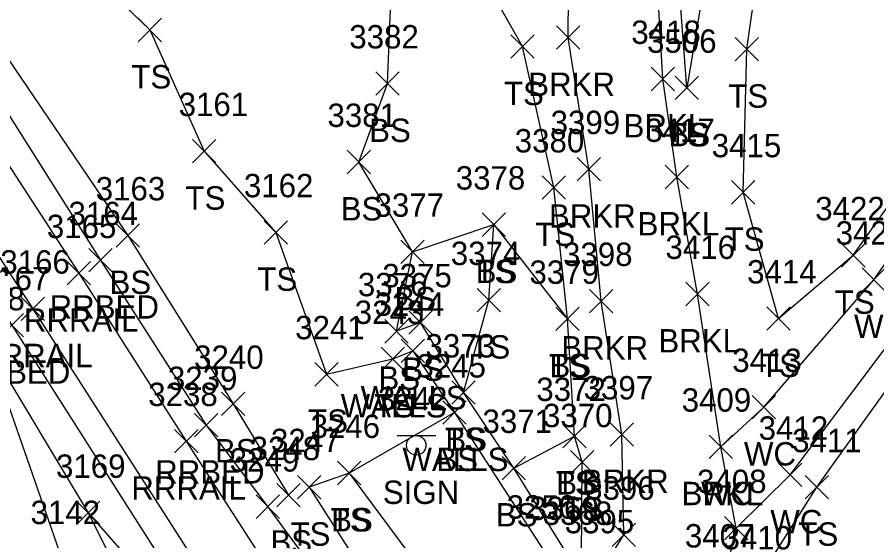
# Model space of a CAD drawing. Extents: x 1505656 to 1508446, y 700805 to 703031.
# Drawn here: x 1506556.2 to 1506629.8, y 701671.8 to 701716.6 of the extents above; entities that cross this region are included whole.
import ezdxf

# ---------------------------------------------------------------- set-up
doc = ezdxf.new("R2010")
doc.units = 0
for name, color, linetype in [('L_A', 7, 'Continuous'), ('L_I', 7, 'Continuous'), ('L_TIC', 7, 'Continuous'), ('LAWE', 7, 'Continuous'), ('LELB', 7, 'Continuous'), ('LWS', 7, 'Continuous'), ('R_A', 7, 'Continuous'), ('R_I', 7, 'Continuous'), ('R_TIC', 7, 'Continuous'), ('RR', 7, 'Continuous'), ('RRB', 7, 'Continuous'), ('S_A', 7, 'Continuous'), ('S_I', 7, 'Continuous'), ('SSGN', 7, 'Continuous')]:
    doc.layers.add(name, color=color, linetype=linetype)

msp = doc.modelspace()

# ---------------------------------------------------------------- linework, layer by layer
at = {"layer": 'L_TIC'}
for points in [[(1506566.599, 701714.48), (1506568.599, 701716.48)], [(1506568.599, 701714.48), (1506566.599, 701716.48)], [(1506602.376, 701713.835), (1506604.376, 701715.835)], [(1506604.376, 701713.835), (1506602.376, 701715.835)], [(1506598.481, 701713.057), (1506600.481, 701715.057)], [(1506600.481, 701713.057), (1506598.481, 701715.057)], [(1506617.679, 701712.834), (1506619.679, 701714.834)], [(1506619.679, 701712.834), (1506617.679, 701714.834)], [(1506610.484, 701710.29), (1506612.484, 701712.29)], [(1506612.484, 701710.29), (1506610.484, 701712.29)], [(1506586.916, 701709.9), (1506588.916, 701711.9)], [(1506588.916, 701709.9), (1506586.916, 701711.9)], [(1506612.533, 701709.53), (1506614.533, 701711.53)], [(1506614.533, 701709.53), (1506612.533, 701711.53)], [(1506612.533, 701709.53), (1506614.533, 701711.53)], [(1506614.533, 701709.53), (1506612.533, 701711.53)], [(1506571.225, 701704.115), (1506573.225, 701706.115)], [(1506573.225, 701704.115), (1506571.225, 701706.115)], [(1506584.481, 701703.187), (1506586.481, 701705.187)], [(1506586.481, 701703.187), (1506584.481, 701705.187)], [(1506604.153, 701702.576), (1506606.153, 701704.576)], [(1506606.153, 701702.576), (1506604.153, 701704.576)], [(1506611.682, 701701.908), (1506613.682, 701703.908)], [(1506613.682, 701701.908), (1506611.682, 701703.908)], [(1506601.164, 701701.007), (1506603.164, 701703.007)], [(1506603.164, 701701.007), (1506601.164, 701703.007)], [(1506617.367, 701700.596), (1506619.367, 701702.596)], [(1506619.367, 701700.596), (1506617.367, 701702.596)], [(1506596.028, 701697.83), (1506598.028, 701699.83)], [(1506598.028, 701697.83), (1506596.028, 701699.83)], [(1506596.028, 701697.83), (1506598.028, 701699.83)], [(1506598.028, 701697.83), (1506596.028, 701699.83)], [(1506564.696, 701696.905), (1506566.696, 701698.905)], [(1506566.696, 701696.905), (1506564.696, 701698.905)], [(1506577.376, 701697.171), (1506579.376, 701699.171)], [(1506579.376, 701697.171), (1506577.376, 701699.171)], [(1506589.073, 701695.505), (1506591.073, 701697.505)], [(1506591.073, 701695.505), (1506589.073, 701697.505)], [(1506589.073, 701695.505), (1506591.073, 701697.505)], [(1506591.073, 701695.505), (1506589.073, 701697.505)], [(1506626.792, 701695.207), (1506628.792, 701697.207)], [(1506628.792, 701695.207), (1506626.792, 701697.207)], [(1506628.543, 701693.124), (1506630.543, 701695.124)], [(1506630.543, 701693.124), (1506628.543, 701695.124)], [(1506613.462, 701691.898), (1506615.462, 701693.898)], [(1506615.462, 701691.898), (1506613.462, 701693.898)], [(1506595.606, 701691.376), (1506597.606, 701693.376)], [(1506597.606, 701691.376), (1506595.606, 701693.376)], [(1506605.208, 701691.295), (1506607.208, 701693.295)], [(1506607.208, 701691.295), (1506605.208, 701693.295)], [(1506602.343, 701689.768), (1506604.343, 701691.768)], [(1506604.343, 701689.768), (1506602.343, 701691.768)], [(1506602.343, 701689.768), (1506604.343, 701691.768)], [(1506604.343, 701689.768), (1506602.343, 701691.768)], [(1506620.395, 701689.798), (1506622.395, 701691.798)], [(1506622.395, 701689.798), (1506620.395, 701691.798)], [(1506620.395, 701689.798), (1506622.395, 701691.798)], [(1506622.395, 701689.798), (1506620.395, 701691.798)], [(1506589.741, 701689.472), (1506591.741, 701691.472)], [(1506591.741, 701689.472), (1506589.741, 701691.472)], [(1506587.708, 701688.708), (1506589.708, 701690.708)], [(1506589.708, 701688.708), (1506587.708, 701690.708)], [(1506589.085, 701687.031), (1506591.085, 701689.031)], [(1506591.085, 701687.031), (1506589.085, 701689.031)], [(1506587.38, 701686.341), (1506589.38, 701688.341)], [(1506589.38, 701686.341), (1506587.38, 701688.341)], [(1506587.38, 701686.341), (1506589.38, 701688.341)], [(1506589.38, 701686.341), (1506587.38, 701688.341)], [(1506581.718, 701685.029), (1506583.718, 701687.029)], [(1506583.718, 701685.029), (1506581.718, 701687.029)], [(1506593.437, 701683.467), (1506595.437, 701685.467)], [(1506595.437, 701683.467), (1506593.437, 701685.467)], [(1506593.437, 701683.467), (1506595.437, 701685.467)], [(1506595.437, 701683.467), (1506593.437, 701685.467)], [(1506573.724, 701682.495), (1506575.724, 701684.495)], [(1506575.724, 701682.495), (1506573.724, 701684.495)], [(1506619.125, 701682.229), (1506621.125, 701684.229)], [(1506621.125, 701682.229), (1506619.125, 701684.229)], [(1506592.664, 701681.754), (1506594.664, 701683.754)], [(1506594.664, 701681.754), (1506592.664, 701683.754)], [(1506592.664, 701681.754), (1506594.664, 701683.754)], [(1506594.664, 701681.754), (1506592.664, 701683.754)], [(1506602.92, 701679.748), (1506604.92, 701681.748)], [(1506604.92, 701679.748), (1506602.92, 701681.748)], [(1506602.92, 701679.748), (1506604.92, 701681.748)], [(1506604.92, 701679.748), (1506602.92, 701681.748)], [(1506606.969, 701679.881), (1506608.969, 701681.881)], [(1506608.969, 701679.881), (1506606.969, 701681.881)], [(1506615.449, 701678.836), (1506617.449, 701680.836)], [(1506617.449, 701678.836), (1506615.449, 701680.836)], [(1506615.449, 701678.836), (1506617.449, 701680.836)], [(1506617.449, 701678.836), (1506615.449, 701680.836)], [(1506597.748, 701677.015), (1506599.748, 701679.015)], [(1506599.748, 701677.015), (1506597.748, 701679.015)], [(1506597.748, 701677.015), (1506599.748, 701679.015)], [(1506599.748, 701677.015), (1506597.748, 701679.015)], [(1506603.58, 701677.51), (1506605.58, 701679.51)], [(1506605.58, 701677.51), (1506603.58, 701679.51)], [(1506583.658, 701676.589), (1506585.658, 701678.589)], [(1506585.658, 701676.589), (1506583.658, 701678.589)], [(1506583.658, 701676.589), (1506585.658, 701678.589)], [(1506585.658, 701676.589), (1506583.658, 701678.589)], [(1506621.379, 701676.433), (1506623.379, 701678.433)], [(1506623.379, 701676.433), (1506621.379, 701678.433)], [(1506580.215, 701675.373), (1506582.215, 701677.373)], [(1506582.215, 701675.373), (1506580.215, 701677.373)], [(1506623.679, 701675.369), (1506625.679, 701677.369)], [(1506625.679, 701675.369), (1506623.679, 701677.369)], [(1506578.462, 701674.693), (1506580.462, 701676.693)], [(1506580.462, 701674.693), (1506578.462, 701676.693)], [(1506561.308, 701673.175), (1506563.308, 701675.175)], [(1506563.308, 701673.175), (1506561.308, 701675.175)], [(1506561.308, 701673.175), (1506563.308, 701675.175)], [(1506563.308, 701673.175), (1506561.308, 701675.175)], [(1506616.756, 701671.874), (1506618.756, 701673.874)], [(1506618.756, 701671.874), (1506616.756, 701673.874)], [(1506616.756, 701671.874), (1506618.756, 701673.874)], [(1506618.756, 701671.874), (1506616.756, 701673.874)], [(1506607.156, 701671.303), (1506609.156, 701673.303)], [(1506609.156, 701671.303), (1506607.156, 701673.303)]]:
    msp.add_lwpolyline(points, dxfattribs=at)
at = {"layer": 'LAWE'}
for points in [[(1506596.391, 701650.813), (1506598.12, 701648.37), (1506605.093, 701653.847), (1506612.387, 701657.736), (1506612.989, 701658.81), (1506616.717, 701668.22), (1506617.756, 701672.874), (1506616.449, 701679.836), (1506614.462, 701692.898), (1506612.682, 701702.908), (1506611.484, 701711.29), (1506610.784, 701723.745), (1506609.981, 701733.422), (1506610.541, 701739.144), (1506612.027, 701741.37), (1506611.447, 701742.461), (1506611.614, 701744.27), (1506603.978, 701743.071), (1506603.748, 701741.133), (1506602.073, 701738.416), (1506602.874, 701733.32), (1506603.244, 701730.11)], [(1506596.391, 701650.813), (1506591.38, 701658.463), (1506600.932, 701662.01), (1506606.351, 701669.434), (1506608.156, 701672.303), (1506607.969, 701680.881), (1506606.208, 701692.295), (1506605.153, 701703.576), (1506603.376, 701714.835), (1506603.473, 701725.818), (1506603.244, 701730.11)], [(1506616.449, 701679.836), (1506620.125, 701683.229), (1506629.543, 701694.124), (1506636.213, 701703.594), (1506642.857, 701712.08), (1506652.659, 701718.496), (1506664.644, 701725.42), (1506671.523, 701720.322), (1506675.199, 701717.48), (1506672.226, 701716.863)], [(1506617.756, 701672.874), (1506622.379, 701677.433), (1506633.021, 701691.578), (1506640.145, 701700.527), (1506645.72, 701709.687), (1506653.703, 701716.822), (1506663.812, 701719.167), (1506668.675, 701716.04), (1506672.226, 701716.863)]]:
    msp.add_lwpolyline(points, dxfattribs=at)
at = {"layer": 'LELB'}
for points in [[(1506208.26, 702225.335), (1506233.066, 702186.127), (1506256.11, 702150.879), (1506281.705, 702110.75), (1506310.98, 702065.972), (1506335.891, 702023.858), (1506362.149, 701986.17), (1506387.438, 701946.028), (1506412.525, 701907.733), (1506436.182, 701872.353), (1506448.776, 701849.495), (1506468, 701820.558), (1506480.93, 701799.854), (1506497.591, 701775.161), (1506503.349, 701767.24), (1506509.308, 701758.888), (1506523.549, 701737.243), (1506530.483, 701722.023), (1506538.471, 701708.022), (1506540.166, 701706.711), (1506553.683, 701688.505), (1506562.308, 701674.175), (1506570.511, 701664.867), (1506574.8, 701654.407)], [(1506521.669, 701765.32), (1506534.779, 701745.544), (1506553.063, 701716.488), (1506565.696, 701697.905), (1506574.724, 701683.495), (1506579.462, 701675.693)], [(1506527.402, 701761.586), (1506538.905, 701748.963), (1506551.137, 701736.558), (1506560.201, 701722.622), (1506567.599, 701715.48), (1506572.225, 701705.115), (1506578.376, 701698.171), (1506582.718, 701686.029), (1506588.38, 701687.341)], [(1506588.454, 701661.532), (1506598.724, 701663.159), (1506604.519, 701670.15), (1506604.58, 701678.51), (1506603.92, 701680.748), (1506603.343, 701690.768), (1506602.164, 701702.007), (1506599.481, 701714.057), (1506595.154, 701721.739), (1506588.389, 701722.251), (1506582.741, 701726.246), (1506582.101, 701731.513), (1506587.69, 701737.804), (1506593.866, 701742.155), (1506598.799, 701744.247), (1506603.709, 701745.876), (1506611.659, 701747.313), (1506624.477, 701749.861), (1506638.605, 701749.732), (1506649.966, 701745.745), (1506670.738, 701751.879), (1506689.354, 701753.592), (1506711.832, 701752.969)], [(1506613.533, 701710.53), (1506612.66, 701722.284), (1506612.628, 701732.407), (1506613.254, 701736.09), (1506614.399, 701738.78)], [(1506621.395, 701690.798), (1506618.367, 701701.596), (1506618.679, 701713.834), (1506620.219, 701724.632), (1506621.544, 701732.69), (1506616.91, 701738.724)], [(1506615.443, 701737.544), (1506615.668, 701723.186), (1506613.533, 701710.53)], [(1506621.395, 701690.798), (1506627.792, 701696.207), (1506634.174, 701705.162), (1506640.084, 701713.732), (1506650.93, 701722.899), (1506658.179, 701731.465), (1506668.982, 701736.006), (1506676.406, 701733.784), (1506676.923, 701732.689), (1506680.821, 701728.207), (1506683.986, 701722.725), (1506680.085, 701718.515)], [(1506591.38, 701658.463), (1506588.454, 701661.532), (1506595.997, 701665.429), (1506603.368, 701670.572), (1506598.748, 701678.015), (1506594.437, 701684.467), (1506590.741, 701690.472), (1506588.708, 701689.708), (1506590.073, 701696.505), (1506585.481, 701704.187), (1506587.916, 701710.9), (1506588.389, 701722.251)], [(1506643.117, 701605.748), (1506639.001, 701618.333), (1506643.622, 701631.74), (1506640.308, 701639.683), (1506633.13, 701645.993), (1506626.147, 701655.591), (1506616.045, 701657.921), (1506619.379, 701668.052), (1506624.679, 701676.369), (1506634.473, 701690.099), (1506642.028, 701699.549), (1506647.355, 701708.592), (1506655.441, 701714.325), (1506661.308, 701715.943), (1506665.202, 701714.807), (1506668.49, 701715.257)], [(1506590.073, 701696.505), (1506597.028, 701698.83), (1506603.343, 701690.768)], [(1506594.437, 701684.467), (1506596.606, 701692.376), (1506597.028, 701698.83)], [(1506577.624, 701650.314), (1506575.348, 701653.176), (1506572.589, 701651.558), (1506569.631, 701655.668), (1506565.277, 701662.326), (1506560.072, 701670.221), (1506553.683, 701688.505)], [(1506593.664, 701682.754), (1506584.658, 701677.589), (1506593.522, 701665.622), (1506589.253, 701663.808)], [(1506598.748, 701678.015), (1506603.92, 701680.748)], [(1506584.658, 701677.589), (1506581.215, 701676.373), (1506589.253, 701663.808)], [(1506562.308, 701674.175), (1506567.78, 701663.323), (1506574.8, 701654.407)]]:
    msp.add_lwpolyline(points, dxfattribs=at)
at = {"layer": 'LWS'}
msp.add_lwpolyline([(1506588.38, 701687.341), (1506590.085, 701688.031), (1506593.664, 701682.754), (1506601.468, 701670.685), (1506593.522, 701665.622), (1506591.016, 701664.938)], dxfattribs=at)
at = {"layer": 'R_TIC'}
for points in [[(1506562.365, 701694.789), (1506564.365, 701696.789)], [(1506564.365, 701694.789), (1506562.365, 701696.789)], [(1506560.515, 701693.679), (1506562.515, 701695.679)], [(1506562.515, 701693.679), (1506560.515, 701695.679)], [(1506556.587, 701690.641), (1506558.587, 701692.641)], [(1506558.587, 701690.641), (1506556.587, 701692.641)], [(1506554.777, 701689.222), (1506556.777, 701691.222)], [(1506556.777, 701689.222), (1506554.777, 701691.222)], [(1506571.4, 701680.686), (1506573.4, 701682.686)], [(1506573.4, 701680.686), (1506571.4, 701682.686)], [(1506569.711, 701679.312), (1506571.711, 701681.312)], [(1506571.711, 701679.312), (1506569.711, 701681.312)], [(1506576.693, 701673.709), (1506578.693, 701675.709)], [(1506578.693, 701673.709), (1506576.693, 701675.709)]]:
    msp.add_lwpolyline(points, dxfattribs=at)
at = {"layer": 'RR'}
for points in [[(1506395.941, 701951.532), (1506421.294, 701912.094), (1506443.947, 701877.066), (1506458.06, 701855.132), (1506477.026, 701825.698), (1506489.95, 701805.704), (1506505.503, 701781.607), (1506516.888, 701763.966), (1506530.738, 701742.303), (1506549.167, 701713.636), (1506561.515, 701694.679), (1506570.711, 701680.312), (1506583.655, 701660.241), (1506594.67, 701642.933), (1506603.159, 701630.088), (1506614.277, 701612.399), (1506629.205, 701589.442), (1506648.851, 701558.788), (1506660.225, 701541.186), (1506675.334, 701517.778), (1506692.154, 701491.324), (1506703.48, 701473.749), (1506714.95, 701455.892)], [(1506391.761, 701949.048), (1506416.431, 701910.499), (1506441.341, 701871.887), (1506453.838, 701852.659), (1506472.446, 701823.579), (1506485.516, 701803.299), (1506501.665, 701778.375), (1506512.787, 701761.072), (1506526.773, 701739.695), (1506545.52, 701710.15), (1506557.587, 701691.641), (1506579.63, 701657.283), (1506590.104, 701641.036), (1506608.441, 701612.672), (1506626.095, 701584.977), (1506633.54, 701573.573), (1506654.337, 701541.007), (1506666.412, 701522.298), (1506688.834, 701487.369), (1506710.86, 701453.158)]]:
    msp.add_lwpolyline(points, dxfattribs=at)
at = {"layer": 'RRB'}
for points in [[(1506218.207, 702231.869), (1506243.423, 702192.986), (1506265.645, 702156.973), (1506291.152, 702118.107), (1506320.482, 702072.195), (1506347.645, 702031.42), (1506371.505, 701993.069), (1506397.737, 701952.642), (1506422.134, 701913.025), (1506446.302, 701877.372), (1506459.904, 701856.601), (1506479.197, 701826.274), (1506491.068, 701808.201), (1506507.805, 701783.164), (1506518.904, 701765.849), (1506532.833, 701744.112), (1506551.138, 701715.117), (1506563.365, 701695.789), (1506572.4, 701681.686), (1506577.693, 701674.709), (1506587.051, 701661.961)], [(1506210.032, 702226.699), (1506235.369, 702188.006), (1506257.817, 702152.359), (1506283.918, 702112.551), (1506312.529, 702067.455), (1506339.769, 702025.985), (1506362.71, 701990.183), (1506390.113, 701948.059), (1506413.744, 701910.016), (1506437.483, 701874.064), (1506451.694, 701851.337), (1506470.612, 701821.885), (1506483.367, 701801.538), (1506500.232, 701776.891), (1506510.87, 701759.997), (1506525.082, 701738.282), (1506533.528, 701723.993), (1506542.091, 701710.784), (1506543.896, 701708.677), (1506555.777, 701690.222), (1506571.644, 701665.343), (1506576.241, 701655.226)]]:
    msp.add_lwpolyline(points, dxfattribs=at)
at = {"layer": 'SSGN'}
for p, q in [((1506588.74, 701680.795), (1506592.073, 701680.795)), ((1506590.387, 701679.961), (1506590.387, 701679.961))]:
    msp.add_line(p, q, dxfattribs=at)
msp.add_circle((1506590.387, 701679.961), 0.833, dxfattribs=at)

# ---------------------------------------------------------------- texts
at = {"layer": 'L_A'}
for s, p in [('TS', (1506566.009, 701710.48)), ('BRKR', (1506599.967, 701709.835)), ('TS', (1506597.89, 701709.057)), ('TS', (1506617.089, 701708.834)), ('BS', (1506586.357, 701705.9)), ('BRKL', (1506608.13, 701706.29)), ('TS', (1506611.943, 701705.53)), ('BS', (1506611.974, 701705.53)), ('TS', (1506570.635, 701700.115)), ('BS', (1506583.922, 701699.187)), ('BRKR', (1506601.743, 701698.576)), ('BRKL', (1506609.328, 701697.908)), ('TS', (1506600.573, 701697.007)), ('TS', (1506616.776, 701696.596)), ('TS', (1506576.786, 701693.171)), ('TS', (1506595.437, 701693.83)), ('BS', (1506595.469, 701693.83)), ('BS', (1506564.137, 701692.905)), ('BS', (1506588.514, 701691.505)), ('BS', (1506588.514, 701691.505)), ('TS', (1506626.202, 701691.207)), ('WC', (1506627.85, 701689.124)), ('TS', (1506595.016, 701687.376)), ('BRKR', (1506602.799, 701687.295)), ('BRKL', (1506611.108, 701687.898)), ('TS', (1506601.752, 701685.768)), ('BS', (1506601.783, 701685.768)), ('TS', (1506619.805, 701685.798)), ('TS', (1506619.805, 701685.798)), ('BS', (1506589.182, 701685.472)), ('BS', (1506587.148, 701684.708)), ('WALLS', (1506585.628, 701683.031)), ('WALLS', (1506583.923, 701682.341)), ('TS', (1506586.789, 701682.341)), ('TS', (1506581.128, 701681.029)), ('TS', (1506592.847, 701679.467)), ('BS', (1506592.878, 701679.467)), ('BS', (1506573.165, 701678.495)), ('WALLS', (1506589.207, 701677.754)), ('BS', (1506592.105, 701677.754)), ('WC', (1506618.432, 701678.229)), ('TS', (1506602.33, 701675.748)), ('BS', (1506602.361, 701675.748)), ('BRKR', (1506604.559, 701675.881)), ('BRKL', (1506613.094, 701674.836)), ('WC', (1506614.756, 701674.836)), ('TS', (1506602.99, 701673.51)), ('TS', (1506583.068, 701672.589)), ('BS', (1506583.099, 701672.589)), ('BS', (1506597.189, 701673.015)), ('BS', (1506597.189, 701673.015)), ('WC', (1506620.686, 701672.433)), ('TS', (1506579.624, 701671.373)), ('TS', (1506623.088, 701671.369)), ('BS', (1506577.903, 701670.693))]:
    msp.add_text(s, height=2, dxfattribs=at).set_placement(p)
at = {"layer": 'L_I'}
for s, p in [('3382', (1506584.656, 701713.9)), ('3418', (1506608.791, 701714.29)), ('3506', (1506610.14, 701713.53)), ('3506', (1506610.14, 701713.53)), ('3161', (1506570.052, 701708.115)), ('3381', (1506582.788, 701707.187)), ('3399', (1506601.885, 701706.576)), ('3417', (1506609.99, 701705.908)), ('3380', (1506598.817, 701705.007)), ('3415', (1506615.674, 701704.596)), ('3378', (1506593.768, 701701.83)), ('3378', (1506593.768, 701701.83)), ('3163', (1506562.956, 701700.905)), ('3162', (1506575.636, 701701.171)), ('3377', (1506586.813, 701699.505)), ('3377', (1506586.813, 701699.505)), ('3422', (1506624.533, 701699.207)), ('3423', (1506626.283, 701697.124)), ('3374', (1506593.346, 701695.376)), ('3416', (1506611.714, 701695.898)), ('3398', (1506602.949, 701695.295)), ('3375', (1506587.481, 701693.472)), ('3379', (1506600.075, 701693.768)), ('3379', (1506600.075, 701693.768)), ('3414', (1506618.703, 701693.798)), ('3414', (1506618.703, 701693.798)), ('3376', (1506585.393, 701692.708)), ('3168', (1506550.943, 701691.505)), ('3168', (1506550.943, 701691.505)), ('3244', (1506586.825, 701691.031)), ('3243', (1506585.12, 701690.341)), ('3243', (1506585.12, 701690.341)), ('3241', (1506580.025, 701689.029)), ('3373', (1506591.177, 701687.467)), ('3373', (1506591.177, 701687.467)), ('3240', (1506571.378, 701686.495)), ('3413', (1506617.432, 701686.229)), ('3245', (1506590.404, 701685.754)), ('3245', (1506590.404, 701685.754)), ('3372', (1506600.66, 701683.748)), ('3372', (1506600.66, 701683.748)), ('3397', (1506604.709, 701683.881)), ('3409', (1506613.102, 701682.836)), ('3409', (1506613.102, 701682.836)), ('3370', (1506601.234, 701681.51)), ('3371', (1506596.055, 701681.015)), ('3371', (1506596.055, 701681.015)), ('3246', (1506581.343, 701680.589)), ('3246', (1506581.343, 701680.589)), ('3412', (1506619.686, 701680.433)), ('3247', (1506577.955, 701679.373)), ('3411', (1506622.553, 701679.369)), ('3248', (1506576.203, 701678.693)), ('3169', (1506559.56, 701677.175)), ('3169', (1506559.56, 701677.175)), ('3408', (1506614.418, 701675.874)), ('3408', (1506614.418, 701675.874)), ('3396', (1506604.842, 701675.303)), ('3250', (1506598.122, 701673.685)), ('3369', (1506600.053, 701673.572)), ('3142', (1506557.379, 701673.221)), ('3142', (1506557.379, 701673.221)), ('3368', (1506601.212, 701673.15)), ('3395', (1506603.091, 701672.434)), ('3407', (1506613.378, 701671.22)), ('3410', (1506616.599, 701671.052))]:
    msp.add_text(s, height=2, dxfattribs=at).set_placement(p)
at = {"layer": 'R_A'}
for s, p in [('RRBED', (1506559.01, 701690.789)), ('RRRAIL', (1506556.806, 701689.679)), ('RRRAIL', (1506552.879, 701686.641)), ('RRBED', (1506551.423, 701685.222)), ('RRBED', (1506568.045, 701676.686)), ('RRRAIL', (1506566.002, 701675.312))]:
    msp.add_text(s, height=2, dxfattribs=at).set_placement(p)
at = {"layer": 'R_I'}
for s, p in [('3164', (1506560.625, 701698.789)), ('3165', (1506558.774, 701697.679)), ('3166', (1506554.792, 701694.641)), ('3167', (1506553.037, 701693.222)), ('3239', (1506569.132, 701684.686)), ('3238', (1506567.451, 701683.312)), ('3249', (1506574.425, 701677.709))]:
    msp.add_text(s, height=2, dxfattribs=at).set_placement(p)
at = {"layer": 'S_A'}
msp.add_text('SIGN', height=2, dxfattribs=at).set_placement((1506587.525, 701674.941))
at = {"layer": 'S_I'}
msp.add_text('3242', height=2, dxfattribs=at).set_placement((1506587.107, 701682.941))

doc.saveas('drawing.dxf')
